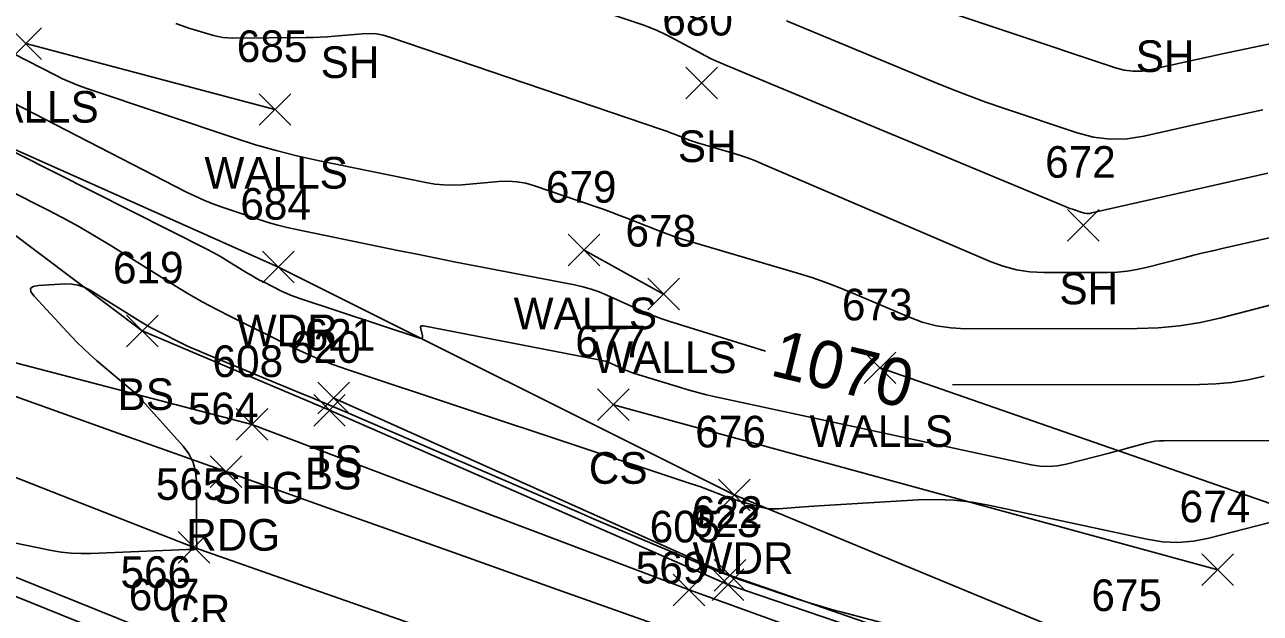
# Model space of a CAD drawing. Extents: x 1592612 to 1596497, y 111838 to 113741.
# Drawn here: x 1592925.8 to 1593003.9, y 113423.7 to 113460.9 of the extents above; entities that cross this region are included whole.
import ezdxf

# ---------------------------------------------------------------- set-up
doc = ezdxf.new("R2010")
doc.units = 0
for name, color, linetype in [('L_A', 7, 'Continuous'), ('L_I', 7, 'Continuous'), ('L_TIC', 7, 'Continuous'), ('LAWA', 7, 'Continuous'), ('LELB', 7, 'Continuous'), ('LSOGCMA', 7, 'Continuous'), ('LSOGCMA_T', 7, 'Continuous'), ('LSOGCMI', 7, 'Continuous'), ('LWS', 7, 'Continuous'), ('P_A', 7, 'Continuous'), ('P_I', 7, 'Continuous'), ('P_TIC', 7, 'Continuous'), ('PEU', 7, 'Continuous'), ('PRC', 7, 'Continuous'), ('PSU', 7, 'Continuous')]:
    doc.layers.add(name, color=color, linetype=linetype)

msp = doc.modelspace()

# ---------------------------------------------------------------- linework, layer by layer
at = {"layer": 'L_TIC'}
for points in [[(1592924.91, 113458.718), (1592926.91, 113460.718)], [(1592926.91, 113458.718), (1592924.91, 113460.718)], [(1592967.627, 113456.223), (1592969.627, 113458.223)], [(1592969.627, 113456.223), (1592967.627, 113458.223)], [(1592940.652, 113454.546), (1592942.652, 113456.546)], [(1592942.652, 113454.546), (1592940.652, 113456.546)], [(1592991.736, 113447.233), (1592993.736, 113449.233)], [(1592993.736, 113447.233), (1592991.736, 113449.233)], [(1592960.193, 113445.656), (1592962.193, 113447.656)], [(1592962.193, 113445.656), (1592960.193, 113447.656)], [(1592940.873, 113444.585), (1592942.873, 113446.585)], [(1592942.873, 113444.585), (1592940.873, 113446.585)], [(1592965.216, 113442.883), (1592967.216, 113444.883)], [(1592967.216, 113442.883), (1592965.216, 113444.883)], [(1592932.267, 113440.549), (1592934.267, 113442.549)], [(1592934.267, 113440.549), (1592932.267, 113442.549)], [(1592978.894, 113438.216), (1592980.894, 113440.216)], [(1592980.894, 113438.216), (1592978.894, 113440.216)], [(1592944.373, 113436.303), (1592946.373, 113438.303)], [(1592946.373, 113436.303), (1592944.373, 113438.303)], [(1592962.047, 113435.886), (1592964.047, 113437.886)], [(1592964.047, 113435.886), (1592962.047, 113437.886)], [(1592944.1, 113435.529), (1592946.1, 113437.529)], [(1592946.1, 113435.529), (1592944.1, 113437.529)], [(1592969.681, 113430.184), (1592971.681, 113432.184)], [(1592971.681, 113430.184), (1592969.681, 113432.184)], [(1592969.416, 113425.097), (1592971.416, 113427.097)], [(1592971.416, 113425.097), (1592969.416, 113427.097)], [(1593000.231, 113425.452), (1593002.231, 113427.452)], [(1593002.231, 113425.452), (1593000.231, 113427.452)], [(1592969.28, 113424.515), (1592971.28, 113426.515)], [(1592971.28, 113424.515), (1592969.28, 113426.515)]]:
    msp.add_lwpolyline(points, dxfattribs=at)
at = {"layer": 'LAWA'}
msp.add_lwpolyline([(1593169.611, 113375.165), (1593118.398, 113387.407), (1593080.143, 113394.184), (1593050.562, 113403.447), (1593019.72, 113413.06), (1592995.657, 113420.841), (1592970.681, 113431.184), (1592941.873, 113445.585), (1592917.884, 113456.286)], dxfattribs=at)
at = {"layer": 'LELB'}
for points in [[(1592908.46, 113460.258), (1592922.596, 113449.566), (1592933.267, 113441.549), (1592945.1, 113436.529), (1592970.28, 113425.515), (1592997.076, 113416.402), (1593023.641, 113407.833), (1593049.418, 113399.686), (1593079.204, 113391.835), (1593097.266, 113387.672), (1593130.658, 113380.878), (1593168.554, 113372.43)], [(1592945.373, 113437.303), (1592970.416, 113426.096), (1592997.179, 113416.812), (1593023.772, 113408.406), (1593049.589, 113400.837), (1593079.367, 113392.638), (1593097.503, 113388.59), (1593131.295, 113382.361), (1593169.279, 113374.833)], [(1593001.231, 113426.452), (1592963.047, 113436.886)]]:
    msp.add_lwpolyline(points, dxfattribs=at)
at = {"layer": 'LSOGCMA'}
for points in [[(1592980.906, 113462.838), (1592994.768, 113458.183), (1592995.328, 113458.036), (1592995.891, 113457.967), (1592996.459, 113457.978), (1592997.03, 113458.068), (1592999.325, 113458.586), (1592999.899, 113458.714), (1593000.473, 113458.84), (1593001.048, 113458.963), (1593001.623, 113459.084), (1593005.243, 113459.837)], [(1592972.647, 113440.266), (1592966.606, 113442.151), (1592966.095, 113442.319), (1592965.589, 113442.503), (1592965.089, 113442.702), (1592964.595, 113442.917), (1592962.631, 113443.807), (1592962.136, 113444.014), (1592961.63, 113444.191), (1592961.115, 113444.338), (1592960.591, 113444.456), (1592954.311, 113445.667), (1592953.088, 113445.905), (1592951.866, 113446.146), (1592950.645, 113446.391), (1592949.424, 113446.639), (1592943.02, 113447.953), (1592942.42, 113448.085), (1592941.825, 113448.236), (1592941.234, 113448.405), (1592940.649, 113448.592), (1592938.316, 113449.375), (1592937.737, 113449.582), (1592937.168, 113449.81), (1592936.607, 113450.059), (1592936.056, 113450.33), (1592922.273, 113457.429)], [(1593004.159, 113438.682), (1593003.15, 113438.455), (1593002.133, 113438.293), (1593001.107, 113438.195), (1593000.073, 113438.161), (1592984.482, 113438.142)]]:
    msp.add_lwpolyline(points, dxfattribs=at)
at = {"layer": 'LSOGCMI'}
for points in [[(1592951.236, 113465.495), (1592964.892, 113460.894), (1592965.351, 113460.728), (1592965.801, 113460.543), (1592966.242, 113460.339), (1592966.675, 113460.115), (1592968.389, 113459.182), (1592968.821, 113458.954), (1592969.258, 113458.738), (1592969.7, 113458.533), (1592970.148, 113458.34), (1592991.442, 113449.471), (1592991.592, 113449.41), (1592991.743, 113449.352), (1592991.895, 113449.297), (1592992.047, 113449.244), (1592992.661, 113449.038), (1592992.814, 113448.997), (1592992.969, 113448.979), (1592993.126, 113448.982), (1592993.283, 113449.006), (1593003.276, 113451.262), (1593004.402, 113451.514)], [(1593004.075, 113455.529), (1593003.001, 113455.299), (1593001.928, 113455.063), (1593000.856, 113454.824), (1592996.569, 113453.856), (1592995.501, 113453.688), (1592994.44, 113453.668), (1592993.387, 113453.796), (1592992.342, 113454.071), (1592987.695, 113455.632), (1592986.577, 113456.018), (1592985.467, 113456.424), (1592984.364, 113456.85), (1592983.268, 113457.295), (1592973.987, 113461.16)], [(1593006.828, 113447.957), (1593001.517, 113446.758), (1593000.915, 113446.619), (1593000.314, 113446.476), (1592999.714, 113446.329), (1592999.115, 113446.177), (1592996.721, 113445.559), (1592996.12, 113445.424), (1592995.515, 113445.327), (1592994.904, 113445.269), (1592994.288, 113445.249), (1592990.238, 113445.244), (1592989.366, 113445.287), (1592988.512, 113445.416), (1592987.676, 113445.633), (1592986.857, 113445.937), (1592972.453, 113452.122), (1592972.017, 113452.301), (1592971.576, 113452.468), (1592971.131, 113452.621), (1592970.681, 113452.76), (1592968.351, 113453.446), (1592968.159, 113453.505), (1592967.968, 113453.569), (1592967.779, 113453.637), (1592967.591, 113453.709), (1592966.843, 113454.007), (1592966.656, 113454.08), (1592966.468, 113454.151), (1592966.278, 113454.22), (1592966.088, 113454.286), (1592948.919, 113460.129), (1592948.494, 113460.25), (1592948.064, 113460.325), (1592947.627, 113460.354), (1592947.186, 113460.338), (1592945.408, 113460.182), (1592944.964, 113460.147), (1592944.519, 113460.121), (1592944.073, 113460.105), (1592943.628, 113460.097), (1592938.973, 113460.062), (1592938.665, 113460.071), (1592938.36, 113460.103), (1592938.058, 113460.157), (1592937.76, 113460.234), (1592936.572, 113460.587), (1592936.276, 113460.677), (1592935.982, 113460.773), (1592935.689, 113460.874), (1592935.399, 113460.981)], [(1592925.153, 113459.068), (1592927.74, 113457.736), (1592928.233, 113457.494), (1592928.734, 113457.271), (1592929.243, 113457.067), (1592929.76, 113456.882), (1592939.145, 113453.73), (1592940.434, 113453.319), (1592941.733, 113452.947), (1592943.043, 113452.616), (1592944.364, 113452.324), (1592951.183, 113450.925), (1592951.754, 113450.829), (1592952.327, 113450.776), (1592952.903, 113450.764), (1592953.481, 113450.794), (1592955.798, 113450.998), (1592956.374, 113451.019), (1592956.942, 113450.98), (1592957.504, 113450.882), (1592958.058, 113450.725), (1592961.885, 113449.422), (1592962.39, 113449.247), (1592962.892, 113449.065), (1592963.392, 113448.877), (1592963.89, 113448.682), (1592965.876, 113447.89), (1592966.374, 113447.698), (1592966.877, 113447.518), (1592967.384, 113447.349), (1592967.894, 113447.192), (1592974.676, 113445.196), (1592975.576, 113444.917), (1592976.466, 113444.611), (1592977.347, 113444.279), (1592978.218, 113443.92), (1592981.683, 113442.432), (1592982.558, 113442.107), (1592983.453, 113441.875), (1592984.367, 113441.736), (1592985.301, 113441.691), (1592996.132, 113441.704), (1592997.479, 113441.747), (1592998.815, 113441.875), (1593000.141, 113442.087), (1593001.456, 113442.383), (1593008.997, 113444.328)], [(1592922.914, 113453.988), (1592937.401, 113446.694), (1592937.712, 113446.533), (1592938.019, 113446.365), (1592938.323, 113446.19), (1592938.622, 113446.009), (1592939.881, 113445.225), (1592940.146, 113445.065), (1592940.415, 113444.911), (1592940.687, 113444.763), (1592940.963, 113444.622), (1592942.073, 113444.072), (1592942.353, 113443.939), (1592942.637, 113443.816), (1592942.925, 113443.704), (1592943.217, 113443.601), (1592950.808, 113441.081), (1592950.902, 113441.063), (1592950.96, 113441.083), (1592950.985, 113441.14), (1592950.975, 113441.234), (1592950.865, 113441.687), (1592950.855, 113441.783), (1592950.881, 113441.846), (1592950.942, 113441.874), (1592951.039, 113441.869), (1592962.124, 113439.731), (1592962.321, 113439.687), (1592962.515, 113439.632), (1592962.705, 113439.565), (1592962.891, 113439.487), (1592963.629, 113439.153), (1592963.815, 113439.072), (1592964.002, 113438.997), (1592964.192, 113438.928), (1592964.385, 113438.865), (1592967.276, 113437.963), (1592967.824, 113437.799), (1592968.375, 113437.647), (1592968.929, 113437.508), (1592969.487, 113437.381), (1592989.439, 113433.081), (1592989.994, 113432.994), (1592990.548, 113432.972), (1592991.1, 113433.015), (1592991.651, 113433.124), (1592994.376, 113433.824), (1592994.665, 113433.899), (1592994.954, 113433.975), (1592995.242, 113434.053), (1592995.53, 113434.132), (1592996.681, 113434.451), (1592996.97, 113434.521), (1592997.262, 113434.571), (1592997.556, 113434.601), (1592997.854, 113434.611), (1593004.526, 113434.619)], [(1592922.412, 113451.644), (1592927.232, 113449.217), (1592928.251, 113448.69), (1592929.256, 113448.14), (1592930.25, 113447.568), (1592931.23, 113446.972), (1592935.352, 113444.407), (1592936.219, 113443.881), (1592937.098, 113443.377), (1592937.989, 113442.894), (1592938.893, 113442.433), (1592942.529, 113440.631), (1592943.445, 113440.196), (1592944.375, 113439.795), (1592945.317, 113439.426), (1592946.274, 113439.09), (1592967.957, 113431.892), (1592968.231, 113431.799), (1592968.504, 113431.704), (1592968.775, 113431.605), (1592969.046, 113431.503), (1592970.125, 113431.09), (1592970.396, 113430.99), (1592970.669, 113430.896), (1592970.945, 113430.809), (1592971.222, 113430.728), (1592972.358, 113430.412), (1592972.642, 113430.347), (1592972.927, 113430.306), (1592973.216, 113430.292), (1592973.506, 113430.302), (1592974.778, 113430.404), (1592975.088, 113430.428), (1592975.397, 113430.45), (1592975.707, 113430.471), (1592976.016, 113430.49), (1592982.292, 113430.863), (1592983.439, 113430.892), (1592984.579, 113430.844), (1592985.713, 113430.718), (1592986.842, 113430.514), (1592996.757, 113428.377), (1592997.738, 113428.223), (1592998.716, 113428.184), (1592999.692, 113428.261), (1593000.666, 113428.453), (1593005.996, 113429.821)], [(1592924.357, 113428.321), (1592927.53, 113427.678), (1592928.149, 113427.572), (1592928.772, 113427.504), (1592929.398, 113427.473), (1592930.027, 113427.481), (1592936.082, 113427.739), (1592936.121, 113427.739), (1592936.16, 113427.739), (1592936.199, 113427.736), (1592936.239, 113427.733), (1592936.437, 113427.709), (1592936.455, 113427.708), (1592936.473, 113427.709), (1592936.491, 113427.712), (1592936.508, 113427.716), (1592936.585, 113427.743), (1592936.599, 113427.747), (1592936.612, 113427.753), (1592936.625, 113427.759), (1592936.638, 113427.765), (1592936.689, 113427.793), (1592936.7, 113427.8), (1592936.708, 113427.81), (1592936.712, 113427.822), (1592936.714, 113427.835), (1592936.707, 113428.149), (1592936.706, 113428.206), (1592936.705, 113428.263), (1592936.704, 113428.32), (1592936.704, 113428.377), (1592936.694, 113432.057), (1592936.64, 113432.669), (1592936.481, 113433.241), (1592936.216, 113433.773), (1592935.847, 113434.264), (1592933.087, 113437.344), (1592933.052, 113437.382), (1592933.017, 113437.421), (1592932.948, 113437.498), (1592932.93, 113437.517), (1592932.911, 113437.535), (1592932.893, 113437.553), (1592932.873, 113437.57), (1592930.372, 113439.688), (1592929.954, 113440.053), (1592929.548, 113440.43), (1592929.154, 113440.819), (1592928.772, 113441.221), (1592926.435, 113443.748), (1592926.236, 113444.023), (1592926.215, 113444.227), (1592926.372, 113444.36), (1592926.706, 113444.42), (1592928.399, 113444.52), (1592928.815, 113444.514), (1592929.214, 113444.445), (1592929.598, 113444.315), (1592929.966, 113444.122), (1592933.105, 113442.167), (1592933.426, 113441.973), (1592933.75, 113441.787), (1592934.079, 113441.609), (1592934.413, 113441.439), (1592935.755, 113440.773), (1592936.092, 113440.61), (1592936.432, 113440.452), (1592936.774, 113440.301), (1592937.119, 113440.155), (1592943.01, 113437.728), (1592944.106, 113437.274), (1592945.2, 113436.815), (1592946.293, 113436.352), (1592947.384, 113435.884), (1592960.873, 113430.066), (1592961.823, 113429.657), (1592962.775, 113429.25), (1592963.727, 113428.845), (1592964.68, 113428.442), (1592969.028, 113426.609), (1592969.717, 113426.327), (1592970.41, 113426.058), (1592971.109, 113425.802), (1592971.813, 113425.559), (1592974.637, 113424.614), (1592975.345, 113424.384), (1592976.057, 113424.165), (1592976.771, 113423.958), (1592977.49, 113423.762), (1592994.983, 113419.143)]]:
    msp.add_lwpolyline(points, dxfattribs=at)
at = {"layer": 'LWS'}
for points in [[(1592941.652, 113455.546), (1592925.91, 113459.718)], [(1592966.216, 113443.883), (1592961.193, 113446.656)], [(1593022.683, 113425.211), (1593008.908, 113429.114), (1592979.894, 113439.216)]]:
    msp.add_lwpolyline(points, dxfattribs=at)
at = {"layer": 'P_TIC'}
for points in [[(1592939.197, 113434.636), (1592941.197, 113436.636)], [(1592941.197, 113434.636), (1592939.197, 113436.636)], [(1592937.557, 113431.654), (1592939.557, 113433.654)], [(1592939.557, 113431.654), (1592937.557, 113433.654)], [(1592935.538, 113426.868), (1592937.538, 113428.868)], [(1592937.538, 113426.868), (1592935.538, 113428.868)], [(1592966.822, 113424.18), (1592968.822, 113426.18)], [(1592968.822, 113424.18), (1592966.822, 113426.18)]]:
    msp.add_lwpolyline(points, dxfattribs=at)
at = {"layer": 'PEU'}
for points in [[(1592911.508, 113442.333), (1592918.265, 113439.915), (1592925.029, 113437.495), (1592931.793, 113435.074), (1592938.557, 113432.654), (1592945.636, 113430.136), (1592952.714, 113427.619), (1592959.793, 113425.101), (1592966.871, 113422.584), (1592974.123, 113420.081), (1592981.374, 113417.579), (1592988.626, 113415.076), (1592995.877, 113412.574), (1593003.018, 113410.299), (1593010.16, 113408.025)], [(1592908.287, 113432.828), (1592914.737, 113430.225), (1592921.277, 113427.585), (1592927.817, 113424.945), (1592934.357, 113422.305), (1592941.59, 113419.989), (1592948.822, 113417.672), (1592956.055, 113415.356), (1592963.287, 113413.04), (1592970.605, 113410.585), (1592977.923, 113408.13), (1592985.241, 113405.675), (1592992.559, 113403.22), (1592999.818, 113401.035), (1593007.077, 113398.85)]]:
    msp.add_lwpolyline(points, dxfattribs=at)
at = {"layer": 'PRC'}
msp.add_lwpolyline([(1592910.112, 113438.221), (1592916.699, 113435.64), (1592923.312, 113433.05), (1592929.925, 113430.459), (1592936.538, 113427.868), (1592943.632, 113425.375), (1592950.725, 113422.881), (1592957.819, 113420.387), (1592964.913, 113417.893), (1592972.273, 113415.465), (1592979.633, 113413.038), (1592986.992, 113410.61), (1592994.352, 113408.182), (1593001.474, 113405.968), (1593008.597, 113403.754)], dxfattribs=at)
at = {"layer": 'PSU'}
for points in [[(1593167.681, 113369.582), (1593139.7, 113376.255), (1593109.821, 113382.695), (1593081.736, 113389.175), (1593053.818, 113397.152), (1593024.821, 113405.619), (1592996.75, 113414.705), (1592967.822, 113425.179), (1592940.197, 113435.636), (1592911.843, 113443.034)], [(1593006.031, 113395.756), (1592998.904, 113398.23), (1592991.777, 113400.703), (1592984.424, 113403.052), (1592977.072, 113405.401), (1592969.72, 113407.75), (1592962.368, 113410.099), (1592955.502, 113412.796), (1592948.636, 113415.493), (1592941.77, 113418.19), (1592934.904, 113420.887), (1592928.153, 113423.606), (1592921.403, 113426.325), (1592914.652, 113429.044), (1592907.917, 113431.757)]]:
    msp.add_lwpolyline(points, dxfattribs=at)

# ---------------------------------------------------------------- texts
at = {"layer": 'L_A'}
for s, p in [('SH', (1592944.54, 113457.538)), ('SH', (1592996.05, 113457.918)), ('WALLS', (1592921.453, 113454.718)), ('SH', (1592967.115, 113452.223)), ('WALLS', (1592937.196, 113450.546)), ('SH', (1592991.225, 113443.233)), ('WALLS', (1592956.737, 113441.656)), ('WDR', (1592939.235, 113440.585)), ('WALLS', (1592961.76, 113438.883)), ('BS', (1592931.708, 113436.549)), ('WALLS', (1592975.437, 113434.216)), ('TS', (1592943.783, 113432.303)), ('CS', (1592961.488, 113431.886)), ('BS', (1592943.541, 113431.529)), ('WDR', (1592968.043, 113426.184))]:
    msp.add_text(s, height=2, dxfattribs=at).set_placement(p)
at = {"layer": 'L_I'}
for s, p in [('680', (1592966.131, 113460.223)), ('685', (1592939.243, 113458.546)), ('672', (1592990.327, 113451.233)), ('679', (1592958.776, 113449.656)), ('684', (1592939.464, 113448.585)), ('678', (1592963.807, 113446.883)), ('619', (1592931.416, 113444.549)), ('673', (1592977.484, 113442.216)), ('621', (1592943.531, 113440.303)), ('620', (1592942.604, 113439.529)), ('677', (1592960.638, 113439.886)), ('676', (1592968.216, 113434.184)), ('674', (1592998.822, 113429.452)), ('622', (1592968.006, 113429.097)), ('623', (1592967.871, 113428.515)), ('675', (1592993.247, 113423.841))]:
    msp.add_text(s, height=2, dxfattribs=at).set_placement(p)
at = {"layer": 'LSOGCMA_T'}
msp.add_text('1070', height=3, rotation=346.18802, dxfattribs=at).set_placement((1592972.861, 113438.763))
at = {"layer": 'P_A'}
for s, p in [('SHG', (1592937.732, 113430.636)), ('RDG', (1592936.046, 113427.654)), ('CR', (1592934.971, 113422.868))]:
    msp.add_text(s, height=2, dxfattribs=at).set_placement(p)
at = {"layer": 'P_I'}
for s, p in [('608', (1592937.709, 113438.636)), ('564', (1592936.148, 113435.654)), ('565', (1592934.128, 113430.868)), ('605', (1592965.334, 113428.18)), ('569', (1592964.454, 113425.584)), ('566', (1592931.893, 113425.305)), ('607', (1592932.415, 113423.887))]:
    msp.add_text(s, height=2, dxfattribs=at).set_placement(p)

doc.saveas('drawing.dxf')
